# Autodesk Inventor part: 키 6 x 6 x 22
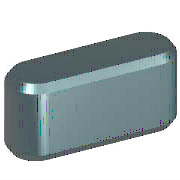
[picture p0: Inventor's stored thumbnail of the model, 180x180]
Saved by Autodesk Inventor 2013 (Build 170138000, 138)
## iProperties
IsCustomPart: 1
Created: 2012-02
Part Number: 키 6 x 6 x 22
Material: 강철, 연강
Description: 키 및 해당 키홈
Document SubType Name: Modeling
Standard: KS B 1311
Designer: mduedu
Standards Organization: KS
Language: ko-KR
Size Designation: 6 x 6 x 22
Categories: <MemberInstance><Categories><Category DisplayName="샤프트 부품" InternalName="7f7aeb1f-a693-4053-b835-cee3144e0d98" Mnemonic="SHFT"><Category DisplayName="키" Interna
Density: 7.86 g/cm^3
Mass: 5.79788 g
Surface Area: 5.294 cm^2
Volume: 0.737644 cm^3
Author: mduedu
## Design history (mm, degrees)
workplane "Work Plane1"
workplane "Work Plane2"
sketch "스케치1"
  geometry: L1 (3, 3)-(19, 3); L2 (19, -3)-(3, -3); L3 (0, 9.4)-(0, -7.4) reference; L4 (-5, 0)-(30, 0) reference; L5 (22, 0)-(22, 7); A1 r 3 centre (3, 0) between (3, 3) and (3, -3); A2 r 3 centre (19, 0) between (19, -3) and (19, 3)
  constraints: 6 end point, 5 point on circle, 4 tangent, 3 point on line, 2 centre point, 1 horizontal, 1 parallel, 1 perpendicular
  dimensions: "d0" = 3 radius of A1 (= 0.5 x PB); "d13" = 3 radius of A2 (= 0.5 x PB); "d14" = 22 distance between parallel lines of L5 L3 (= NLG)
extrude "본체1" new body sketch "스케치1" taper "d3" = 0 deg; stored distance "d4" = 10
workplane "Work Plane3"
body "Solid1"
chamfer "모따기1" distance "d8" = 0.4 (= PHH); stored, may be unused: second distance "d9" = 0.4 (= PHH), angle "d15" = 45 deg
other parameters: "d1" = -3.5 (= -PNT), "d2" = 2.5 (= PH - PNT), "NLG" = 22 [user parameter; used in 3 equation terms], "PB" = 6 [user parameter; used in 2 equation terms], "PNT" = 3.5 [user parameter; used in 2 equation terms], "PH" = 6 [user parameter; used in 1 equation term], "PHH" = 0.4 [user parameter; used in 2 equation terms], "d10" = 0, "d16" = 0, "d17" = 0, "d18" = 0, "WDMIN" = 17 [user parameter], "PLB2" = 22 (= NLG) [user parameter], "WDMAX" = 22 [user parameter], "PLB1" = 22 (= NLG) [user parameter], "RR" = 0.16 [user parameter], "PUEB" = 2.8 [user parameter]
